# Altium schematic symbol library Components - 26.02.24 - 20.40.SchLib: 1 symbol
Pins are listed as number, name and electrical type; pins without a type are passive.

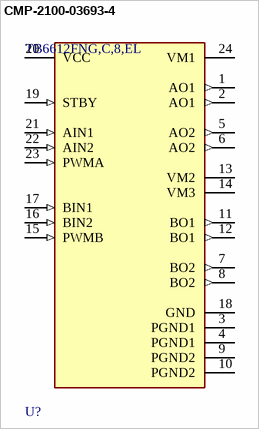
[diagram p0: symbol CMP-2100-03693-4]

## CMP-2100-03693-4
designator U?, comment TB6612FNG,C,8,EL
IC MOTOR DRIVER 2.7V-5.5V 24SSOP; Logic Function: AND GATE; Interface: Parallel; Operating Supply Voltage: 3V; Max Supply Voltage: 5.5V; Output Current: 1A; Min Supply Voltage: 2.7V; Number of Outputs: 2
footprint FP-SSOP24-P-300-0_65A-IPC_C
footprint FP-SSOP24-P-300-0_65A-IPC_A
footprint FP-SSOP24-P-300-0_65A-IPC_B
footprint FP-SSOP24-P-300-0_65A-MFG
pins: 1 AO1 (out), 2 AO1 (out), 3 PGND1 (power), 4 PGND1 (power), 5 AO2 (out), 6 AO2 (out), 7 BO2 (out), 8 BO2 (out), 9 PGND2 (power), 10 PGND2 (power), 11 BO1 (out), 12 BO1 (out), 13 VM2 (power), 14 VM3 (power), 15 PWMB (in), 16 BIN2 (in), 17 BIN1 (in), 18 GND (power), 19 STBY (in), 20 VCC (power), 21 AIN1 (in), 22 AIN2 (in), 23 PWMA (in), 24 VM1 (power)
